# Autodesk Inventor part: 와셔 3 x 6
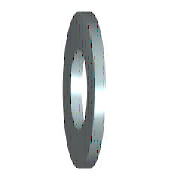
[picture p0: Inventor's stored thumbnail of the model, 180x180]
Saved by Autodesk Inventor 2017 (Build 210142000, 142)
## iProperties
IsCustomPart: 0
Created: 2012-02
Part Number: 와셔 3 x 6
Material: 강철, 연강
Description: 평면 와셔
Document SubType Name: Modeling
Standard: KS B 1326
Designer: mduedu
Standards Organization: KS
Language: ko-KR
Size Designation: 3x6
Categories: <MemberInstance><Categories><Category DisplayName="조임쇠" InternalName="e4da775c-781d-43d5-af7c-5136215cf5a6" Mnemonic="FSTN"><Category DisplayName="와셔" InternalN
Density: 7.86 g/cm^3
Mass: 0.0795112 g
Surface Area: 0.54915 cm^2
Volume: 0.0101159 cm^3
Appearance: 파란색 - 벽 페인트 - 광택
Author: mduedu
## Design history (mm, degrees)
sketch "스케치"
  geometry: C1 r 3 at (0, 0); C2 r 1.6 at (0, 0); 1 further point
  constraints: 2 centre point, 2 coincident
  dimensions: "d0" = 3.2 diameter of C2 (= SD1); "d1" = 6 diameter of C1 (= SD2)
extrude "본체" new body sketch "스케치" distance "d2" = 0.5 (= SD); taper "d3" = 0 deg
workaxis "Work Axis1"
workplane "Work Plane1"
body "Solid1"
other parameters: "SD1" = 3.2 [user parameter; used in 1 equation term], "SD2" = 6 [user parameter; used in 1 equation term], "SD" = 0.5 [user parameter; used in 1 equation term], "d4" = 0, "d5" = 0, "d6" = 0, "d7" = 0, "NND" = 3 [user parameter]
